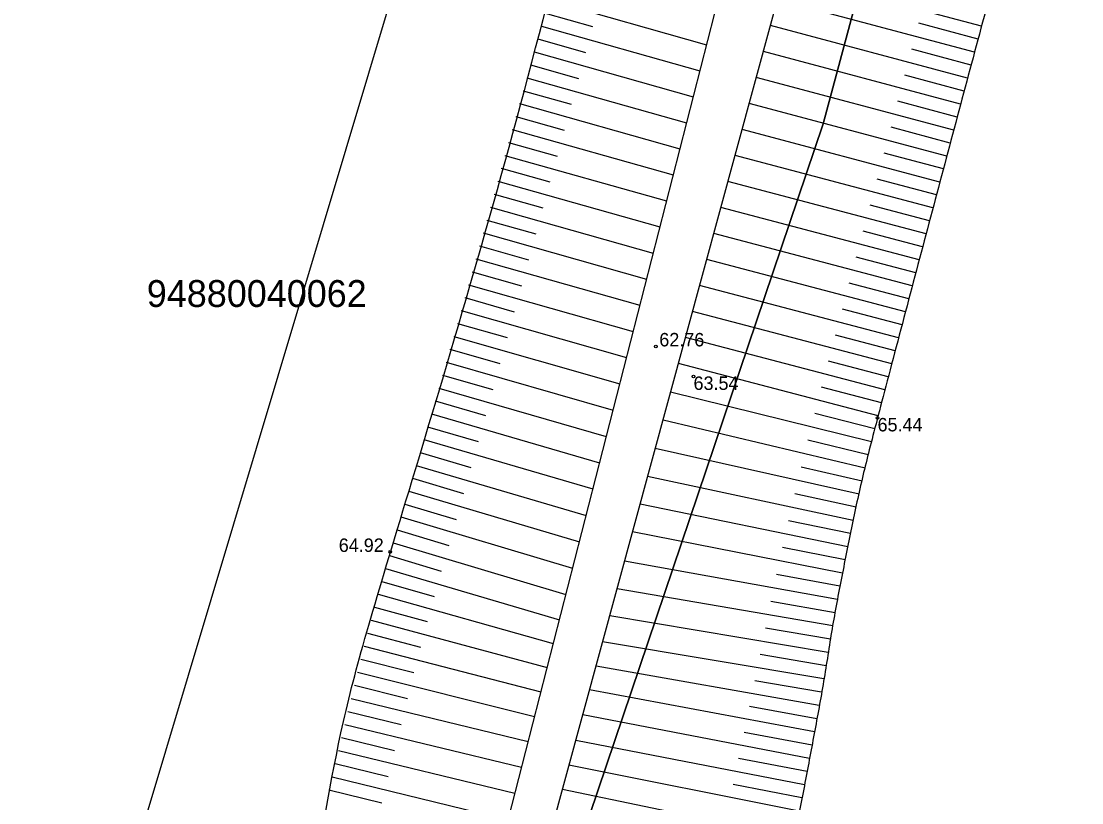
# Model space of a CAD drawing. Extents: x 616607 to 617499, y 408385 to 409695.
# Drawn here: x 617215.1 to 617254.55, y 409366.67 to 409395.75 of the extents above; entities that cross this region are included whole.
import ezdxf

# ---------------------------------------------------------------- set-up
doc = ezdxf.new("R2010")
doc.units = 0
for name, color, linetype in [('HIDG_GRAV_####_####_#', 7, 'Continuous'), ('RAMI_UZMR_####_####_#', 7, 'Continuous'), ('RELJ_AATZ_####_TKST_#', 7, 'Continuous'), ('RELJ_ELEM_####_####_#', 7, 'Continuous'), ('RELJ_NOGA_####_####_#', 7, 'Continuous'), ('ROBZ_PROJ_####_####_#', 7, 'Continuous'), ('ROBZ_PROJ_####_TKST_#', 7, 'Continuous'), ('ROBZ_UZMR_####_####_#', 7, 'Continuous')]:
    doc.layers.add(name, color=color, linetype=linetype)

# ---------------------------------------------------------------- blocks, each defined once
blk = doc.blocks.new('PKT')
at = {"layer": 'RELJ_ELEM_####_####_#'}
blk.add_circle((0, 0), 0.05, dxfattribs=at)

msp = doc.modelspace()

# ---------------------------------------------------------------- linework, layer by layer
at = {"layer": 'HIDG_GRAV_####_####_#'}
for points in [[(617196.049, 409072.553), (617193.886, 409072.979), (617195.921, 409087.874), (617195.921, 409087.874), (617199.518, 409112.516), (617194.569, 409134.842), (617162.019, 409207.474), (617151.93, 409229.107), (617149.428, 409241.28), (617152.359, 409253.938), (617188.564, 409303.055), (617197.968, 409312.659), (617223.456, 409346.169), (617232.567, 409363.51), (617247.671, 409422.509), (617276.576, 409461.456), (617285.007, 409472.526), (617327.765, 409527.3)], [(617198.671, 409072.074), (617200.929, 409072.435), (617202.532, 409075.622), (617201.237, 409087.874), (617202.422, 409112.516), (617197.415, 409136.544), (617162.613, 409207.758), (617153.021, 409229.447), (617150.525, 409241.262), (617153.298, 409253.658), (617189.431, 409302.264), (617198.754, 409312.12), (617224.478, 409345.652), (617234.105, 409363.027), (617250.009, 409421.44), (617285.914, 409471.848), (617328.6, 409526.531)]]:
    msp.add_lwpolyline(points, dxfattribs=at)
at = {"layer": 'RAMI_UZMR_####_####_#'}
msp.add_lwpolyline([(617101.571, 408748.246), (617213.472, 409074.039), (617215.883, 409140.56), (617165.121, 409241.478), (617252.137, 409353.424), (617269.572, 409425.099), (617332.631, 409510.312), (617439.945, 409622.037), (617425.373, 409635.959), (617242.079, 409440.82), (617216.614, 409355.716), (617136.613, 409246.751), (617191.828, 409115.62), (617145.545, 408952.8)], dxfattribs=at)
at = {"layer": 'RELJ_NOGA_####_####_#'}
for p, q in [((617250.823, 409395.565), (617243.5, 409397.533)), ((617234.728, 409396.533), (617240.594, 409394.866)), ((617250.564, 409394.599), (617243.236, 409396.564)), ((617234.592, 409396.052), (617236.355, 409395.551)), ((617234.455, 409395.571), (617234.454, 409395.572)), ((617234.455, 409395.571), (617240.347, 409393.901)), ((617250.306, 409393.633), (617242.973, 409395.595)), ((617250.694, 409395.082), (617248.496, 409395.672)), ((617250.823, 409395.565), (617250.824, 409395.565)), ((617234.319, 409395.09), (617234.319, 409395.09)), ((617234.319, 409395.09), (617236.09, 409394.588)), ((617250.694, 409395.082), (617250.694, 409395.082)), ((617250.435, 409394.116), (617248.236, 409394.705)), ((617234.183, 409394.609), (617234.182, 409394.61)), ((617234.183, 409394.609), (617240.1, 409392.936)), ((617250.048, 409392.667), (617242.709, 409394.625)), ((617250.564, 409394.599), (617250.565, 409394.599)), ((617234.046, 409394.128), (617234.046, 409394.128)), ((617234.046, 409394.128), (617235.825, 409393.625)), ((617250.435, 409394.116), (617250.435, 409394.116)), ((617233.91, 409393.647), (617233.909, 409393.647)), ((617233.91, 409393.647), (617239.853, 409391.971)), ((617249.79, 409391.701), (617242.446, 409393.66)), ((617250.177, 409393.15), (617247.976, 409393.739)), ((617250.306, 409393.633), (617250.307, 409393.633)), ((617233.775, 409393.166), (617233.774, 409393.166)), ((617233.775, 409393.166), (617235.561, 409392.662)), ((617250.177, 409393.15), (617250.177, 409393.15)), ((617233.639, 409392.685), (617233.638, 409392.685)), ((617233.639, 409392.685), (617239.605, 409391.002)), ((617249.533, 409390.735), (617242.182, 409392.691)), ((617249.919, 409392.184), (617247.716, 409392.772)), ((617250.048, 409392.667), (617250.049, 409392.667)), ((617233.503, 409392.203), (617233.503, 409392.203)), ((617233.503, 409392.203), (617235.297, 409391.697)), ((617249.919, 409392.184), (617249.919, 409392.184)), ((617233.367, 409391.722), (617233.366, 409391.722)), ((617233.367, 409391.722), (617239.357, 409390.032)), ((617249.275, 409389.768), (617241.919, 409391.726)), ((617249.661, 409391.218), (617247.457, 409391.805)), ((617249.79, 409391.701), (617249.791, 409391.701)), ((617233.232, 409391.241), (617233.231, 409391.241)), ((617233.232, 409391.241), (617235.032, 409390.733)), ((617249.661, 409391.218), (617249.662, 409391.218)), ((617233.096, 409390.76), (617233.095, 409390.76)), ((617233.096, 409390.76), (617239.109, 409389.065)), ((617249.018, 409388.802), (617241.655, 409390.757)), ((617249.404, 409390.252), (617247.198, 409390.839)), ((617249.533, 409390.735), (617249.534, 409390.734)), ((617232.96, 409390.278), (617232.96, 409390.278)), ((617232.96, 409390.278), (617234.768, 409389.769)), ((617249.404, 409390.252), (617249.404, 409390.251)), ((617232.825, 409389.797), (617232.824, 409389.797)), ((617232.825, 409389.797), (617238.861, 409388.096)), ((617248.762, 409387.835), (617241.392, 409389.792)), ((617249.147, 409389.285), (617246.939, 409389.873)), ((617249.275, 409389.768), (617249.276, 409389.768)), ((617232.689, 409389.316), (617232.689, 409389.316)), ((617232.689, 409389.316), (617234.504, 409388.804)), ((617249.147, 409389.285), (617249.147, 409389.285)), ((617232.553, 409388.835), (617232.552, 409388.835)), ((617232.553, 409388.835), (617238.612, 409387.124)), ((617248.505, 409386.869), (617241.128, 409388.822)), ((617248.89, 409388.319), (617246.68, 409388.905)), ((617249.018, 409388.802), (617249.019, 409388.802)), ((617232.417, 409388.353), (617232.417, 409388.354)), ((617232.417, 409388.353), (617234.239, 409387.839)), ((617248.633, 409387.352), (617246.422, 409387.939)), ((617248.89, 409388.319), (617248.89, 409388.319)), ((617232.282, 409387.872), (617232.281, 409387.873)), ((617232.282, 409387.872), (617238.363, 409386.151)), ((617248.249, 409385.902), (617240.866, 409387.857)), ((617248.762, 409387.835), (617248.763, 409387.835)), ((617232.145, 409387.391), (617232.145, 409387.391)), ((617232.145, 409387.391), (617233.974, 409386.874)), ((617248.633, 409387.352), (617248.634, 409387.352)), ((617232.009, 409386.91), (617232.008, 409386.91)), ((617232.009, 409386.91), (617238.115, 409385.182)), ((617247.994, 409384.935), (617240.602, 409386.888)), ((617248.377, 409386.386), (617246.163, 409386.972)), ((617248.505, 409386.869), (617248.506, 409386.869)), ((617231.873, 409386.429), (617231.873, 409386.429)), ((617231.873, 409386.429), (617233.708, 409385.908)), ((617248.377, 409386.386), (617248.377, 409386.386)), ((617248.121, 409385.419), (617245.905, 409386.004)), ((617231.736, 409385.948), (617231.735, 409385.948)), ((617231.736, 409385.948), (617237.866, 409384.208)), ((617247.738, 409383.969), (617240.338, 409385.919)), ((617248.249, 409385.902), (617248.25, 409385.902)), ((617231.6, 409385.467), (617231.599, 409385.467)), ((617231.6, 409385.467), (617233.442, 409384.942)), ((617248.121, 409385.419), (617248.122, 409385.419)), ((617231.463, 409384.986), (617231.462, 409384.986)), ((617231.463, 409384.986), (617237.616, 409383.233)), ((617247.484, 409383.002), (617240.074, 409384.949)), ((617247.866, 409384.452), (617245.647, 409385.038)), ((617247.994, 409384.935), (617247.995, 409384.935)), ((617231.325, 409384.505), (617231.325, 409384.505)), ((617231.325, 409384.505), (617233.175, 409383.977)), ((617247.866, 409384.452), (617247.866, 409384.452)), ((617231.188, 409384.025), (617231.187, 409384.025)), ((617231.188, 409384.025), (617237.366, 409382.255)), ((617247.611, 409383.485), (617245.389, 409384.069)), ((617247.23, 409382.034), (617239.81, 409383.978)), ((617247.738, 409383.969), (617247.739, 409383.968)), ((617231.05, 409383.544), (617231.05, 409383.544)), ((617231.05, 409383.544), (617232.908, 409383.012)), ((617247.611, 409383.485), (617247.611, 409383.485)), ((617230.912, 409383.063), (617230.911, 409383.064)), ((617230.912, 409383.063), (617237.117, 409381.281)), ((617246.976, 409381.067), (617239.547, 409383.014)), ((617247.357, 409382.518), (617245.133, 409383.103)), ((617247.484, 409383.002), (617247.485, 409383.001)), ((617230.774, 409382.583), (617230.774, 409382.583)), ((617230.774, 409382.583), (617232.639, 409382.045)), ((617247.357, 409382.518), (617247.357, 409382.518)), ((617230.636, 409382.103), (617230.635, 409382.103)), ((617230.636, 409382.103), (617236.865, 409380.299)), ((617247.103, 409381.551), (617244.876, 409382.134)), ((617247.23, 409382.034), (617247.231, 409382.034)), ((617230.497, 409381.622), (617230.496, 409381.622)), ((617230.497, 409381.622), (617232.37, 409381.08)), ((617246.728, 409380.098), (617239.258, 409381.951)), ((617247.103, 409381.551), (617247.103, 409381.551)), ((617230.357, 409381.142), (617230.356, 409381.142)), ((617230.357, 409381.142), (617236.615, 409379.323)), ((617246.492, 409379.127), (617238.975, 409380.911)), ((617246.851, 409380.583), (617244.617, 409381.156)), ((617246.976, 409381.067), (617246.977, 409381.067)), ((617230.218, 409380.662), (617230.217, 409380.662)), ((617230.218, 409380.662), (617232.099, 409380.113)), ((617246.851, 409380.583), (617246.851, 409380.583)), ((617230.077, 409380.182), (617230.076, 409380.182)), ((617230.077, 409380.182), (617236.365, 409378.346)), ((617246.609, 409379.613), (617244.362, 409380.161)), ((617246.728, 409380.098), (617246.729, 409380.098)), ((617229.937, 409379.702), (617229.937, 409379.702)), ((617229.937, 409379.702), (617231.827, 409379.147)), ((617246.267, 409378.152), (617238.685, 409379.848)), ((617246.609, 409379.613), (617246.609, 409379.613)), ((617229.796, 409379.222), (617229.795, 409379.223)), ((617229.796, 409379.222), (617236.112, 409377.359)), ((617246.378, 409378.64), (617244.114, 409379.164)), ((617246.492, 409379.127), (617246.493, 409379.126)), ((617229.655, 409378.743), (617229.654, 409378.743)), ((617229.655, 409378.743), (617231.555, 409378.182)), ((617246.052, 409377.176), (617238.402, 409378.81)), ((617246.378, 409378.64), (617246.378, 409378.64)), ((617229.513, 409378.263), (617229.512, 409378.264)), ((617229.513, 409378.263), (617235.862, 409376.38)), ((617246.158, 409377.664), (617243.874, 409378.166)), ((617246.267, 409378.152), (617246.268, 409378.152)), ((617229.37, 409377.784), (617229.37, 409377.784)), ((617229.37, 409377.784), (617231.281, 409377.217)), ((617245.846, 409376.197), (617238.122, 409377.78)), ((617229.227, 409377.305), (617229.227, 409377.305)), ((617229.227, 409377.305), (617235.611, 409375.399)), ((617246.158, 409377.664), (617246.158, 409377.664)), ((617245.948, 409376.687), (617243.642, 409377.167)), ((617246.052, 409377.176), (617246.053, 409377.175)), ((617229.084, 409376.826), (617229.084, 409376.826)), ((617229.084, 409376.826), (617231.004, 409376.249)), ((617245.65, 409375.216), (617237.843, 409376.755)), ((617245.948, 409376.687), (617245.948, 409376.687)), ((617228.94, 409376.347), (617228.939, 409376.347)), ((617228.94, 409376.347), (617235.36, 409374.418)), ((617245.747, 409375.707), (617243.417, 409376.173)), ((617245.846, 409376.197), (617245.847, 409376.197)), ((617228.796, 409375.868), (617228.796, 409375.868)), ((617228.796, 409375.868), (617230.727, 409375.285)), ((617245.747, 409375.707), (617245.747, 409375.707)), ((617228.653, 409375.389), (617228.652, 409375.39)), ((617228.653, 409375.389), (617235.119, 409373.477)), ((617245.465, 409374.234), (617237.546, 409375.665)), ((617245.556, 409374.725), (617243.197, 409375.17)), ((617245.65, 409375.216), (617245.651, 409375.216)), ((617228.513, 409374.909), (617228.513, 409374.909)), ((617228.513, 409374.909), (617230.461, 409374.346)), ((617245.292, 409373.249), (617237.266, 409374.635)), ((617245.556, 409374.725), (617245.556, 409374.725)), ((617228.376, 409374.428), (617228.375, 409374.428)), ((617228.376, 409374.428), (617234.893, 409372.596)), ((617245.377, 409373.741), (617242.985, 409374.16)), ((617245.465, 409374.234), (617245.466, 409374.233)), ((617228.243, 409373.946), (617228.243, 409373.946)), ((617228.243, 409373.946), (617230.205, 409373.412)), ((617245.377, 409373.741), (617245.378, 409373.741)), ((617228.113, 409373.464), (617228.112, 409373.464)), ((617228.113, 409373.464), (617234.664, 409371.701)), ((617245.124, 409372.263), (617236.993, 409373.633)), ((617227.985, 409372.98), (617227.984, 409372.98)), ((617227.985, 409372.98), (617229.955, 409372.465)), ((617245.208, 409372.756), (617242.784, 409373.169)), ((617245.292, 409373.249), (617245.293, 409373.249)), ((617244.958, 409371.277), (617236.729, 409372.664)), ((617245.208, 409372.756), (617245.208, 409372.756)), ((617227.859, 409372.496), (617227.858, 409372.497)), ((617227.859, 409372.496), (617234.433, 409370.797)), ((617245.041, 409371.77), (617242.587, 409372.184)), ((617245.124, 409372.263), (617245.125, 409372.263)), ((617227.735, 409372.012), (617227.735, 409372.012)), ((617227.735, 409372.012), (617229.71, 409371.513)), ((617244.789, 409370.291), (617236.482, 409371.758)), ((617245.041, 409371.77), (617245.042, 409371.77)), ((617227.613, 409371.527), (617227.612, 409371.527)), ((617227.613, 409371.527), (617234.197, 409369.876)), ((617227.492, 409371.042), (617227.492, 409371.042)), ((617227.492, 409371.042), (617229.468, 409370.553)), ((617244.874, 409370.784), (617242.393, 409371.209)), ((617244.958, 409371.277), (617244.959, 409371.277)), ((617244.611, 409369.307), (617236.241, 409370.873)), ((617244.874, 409370.784), (617244.875, 409370.784)), ((617227.373, 409370.556), (617227.372, 409370.557)), ((617227.373, 409370.556), (617233.959, 409368.947)), ((617244.701, 409369.799), (617242.198, 409370.249)), ((617244.789, 409370.291), (617244.79, 409370.291)), ((617227.254, 409370.071), (617227.254, 409370.071)), ((617227.254, 409370.071), (617229.229, 409369.59)), ((617244.426, 409368.325), (617235.988, 409369.941)), ((617244.701, 409369.799), (617244.702, 409369.799)), ((617227.136, 409369.585), (617227.135, 409369.585)), ((617227.136, 409369.585), (617233.715, 409367.992)), ((617227.019, 409369.099), (617227.019, 409369.099)), ((617227.019, 409369.099), (617228.99, 409368.621)), ((617244.237, 409367.343), (617235.73, 409368.994)), ((617244.519, 409368.816), (617241.997, 409369.291)), ((617244.611, 409369.307), (617244.612, 409369.307)), ((617226.901, 409368.613), (617226.9, 409368.613)), ((617226.901, 409368.613), (617233.466, 409367.024)), ((617244.519, 409368.816), (617244.519, 409368.816)), ((617244.332, 409367.834), (617241.789, 409368.321)), ((617244.426, 409368.325), (617244.427, 409368.324)), ((617226.784, 409368.127), (617226.783, 409368.127)), ((617226.784, 409368.127), (617228.751, 409367.65)), ((617244.043, 409366.362), (617235.477, 409368.065)), ((617244.332, 409367.834), (617244.332, 409367.833)), ((617226.666, 409367.641), (617226.665, 409367.641)), ((617226.666, 409367.641), (617233.215, 409366.043)), ((617226.547, 409367.155), (617226.546, 409367.155)), ((617226.547, 409367.155), (617228.509, 409366.672)), ((617243.845, 409365.381), (617235.231, 409367.161)), ((617244.14, 409366.852), (617241.579, 409367.355)), ((617244.237, 409367.343), (617244.238, 409367.342)), ((617244.14, 409366.852), (617244.141, 409366.852))]:
    msp.add_line(p, q, dxfattribs=at)
for points in [[(617148.095, 409250.281), (617149.367, 409254.282), (617150.639, 409258.284), (617151.912, 409262.285), (617156.597, 409277.022), (617171.021, 409286.603), (617180.379, 409298.915), (617194.802, 409317.89), (617212.921, 409334.355), (617223.034, 409356.295), (617225.913, 409362.541), (617226.817, 409369.327), (617228.782, 409375.821), (617233.86, 409392.605), (617237.843, 409409.628), (617244.376, 409426.063), (617252.258, 409445.895), (617268.673, 409460.708), (617281.86, 409477.296), (617294.583, 409493.301), (617307.725, 409508.821), (617320.496, 409524.825), (617320.543, 409524.885), (617320.584, 409524.948), (617320.623, 409525.013), (617320.843, 409525.374), (617320.906, 409525.909), (617320.728, 409526.275), (617320.636, 409526.463), (617320.388, 409526.567), (617320.294, 409526.764), (617319.61, 409528.184), (617318.926, 409529.604), (617318.242, 409531.024)], [(617336.806, 409523.735), (617334.087, 409521.174), (617331.368, 409518.613), (617328.65, 409516.053), (617321.193, 409509.03), (617314.57, 409501.094), (617308.568, 409492.793), (617305.546, 409488.614), (617302.537, 409484.426), (617299.516, 409480.247), (617296.49, 409476.063), (617293.469, 409471.875), (617290.436, 409467.695), (617287.772, 409464.025), (617284.965, 409460.461), (617282.252, 409456.826), (617279.55, 409453.205), (617276.887, 409449.558), (617274.256, 409445.882), (617271.624, 409442.206), (617269.17, 409438.414), (617266.782, 409434.573), (617265.581, 409432.642), (617264.455, 409430.674), (617263.346, 409428.69), (617262.228, 409426.69), (617261.169, 409424.668), (617260.166, 409422.606), (617258.56, 409419.302), (617257.132, 409415.931), (617255.903, 409412.47), (617254.682, 409409.035), (617253.531, 409405.585), (617252.579, 409402.073), (617251.627, 409398.563), (617250.683, 409395.052), (617249.746, 409391.538), (617248.81, 409388.023), (617247.876, 409384.508), (617246.956, 409380.989), (617246.456, 409379.078), (617246.028, 409377.149), (617245.649, 409375.21), (617245.269, 409373.268), (617244.984, 409371.31), (617244.622, 409369.366), (617244.259, 409367.42), (617243.878, 409365.48), (617243.456, 409363.545), (617243.245, 409362.576), (617242.967, 409361.625), (617242.691, 409360.672), (617242.413, 409359.713), (617242.093, 409358.772), (617241.734, 409357.838), (617241.092, 409356.173), (617240.315, 409354.578), (617239.389, 409353.048), (617238.465, 409351.519), (617237.498, 409350.034), (617236.402, 409348.636), (617235.3, 409347.23), (617234.195, 409345.828), (617233.083, 409344.431), (617231.973, 409343.038), (617230.863, 409341.647), (617229.743, 409340.262), (617227.764, 409337.815), (617225.693, 409335.438), (617223.461, 409333.217), (617221.215, 409330.983), (617218.873, 409328.856), (617216.607, 409326.646), (617214.346, 409324.442), (617212.093, 409322.231), (617209.875, 409319.98), (617208.771, 409318.86), (617207.791, 409317.635), (617206.772, 409316.432), (617205.753, 409315.229), (617204.825, 409314.017), (617203.96, 409312.646), (617203.768, 409312.342), (617203.633, 409312.004), (617203.62, 409311.655), (617203.607, 409311.284), (617203.603, 409310.913), (617203.599, 409310.542), (617203.595, 409310.167), (617203.603, 409309.793), (617203.596, 409309.419), (617203.588, 409309.066), (617203.48, 409308.714), (617203.309, 409308.4), (617202.615, 409307.13), (617201.9, 409305.914), (617201.16, 409304.689), (617200.419, 409303.462), (617199.689, 409302.232), (617198.921, 409301.021), (617197.385, 409298.6), (617195.744, 409296.251), (617194.012, 409293.966), (617188.331, 409286.47), (617182.548, 409279.072), (617176.617, 409271.78), (617175.091, 409269.904), (617173.565, 409268.03), (617172.006, 409266.181), (617170.46, 409264.348), (617168.875, 409262.548), (617167.326, 409260.717), (617165.749, 409258.854), (617164.19, 409256.978), (617162.652, 409255.082), (617161.86, 409254.106), (617161.109, 409253.1), (617160.341, 409252.105), (617159.552, 409251.081), (617158.796, 409250.055), (617158.061, 409248.97), (617157.091, 409247.54), (617156.549, 409245.874), (617156.301, 409244.175), (617156.178, 409243.327), (617156.153, 409242.478), (617156.175, 409241.631), (617156.198, 409240.798), (617156.24, 409239.966), (617156.347, 409239.134), (617156.709, 409236.311), (617157.141, 409233.481), (617158.294, 409230.866), (617161.329, 409223.986), (617164.552, 409217.339), (617167.894, 409210.677), (617170.758, 409204.966), (617173.578, 409199.236), (617176.506, 409193.56), (617179.423, 409187.907), (617182.384, 409182.277), (617185.301, 409176.624), (617188.243, 409170.922), (617191.171, 409165.213), (617194.071, 409159.489), (617195.541, 409156.585), (617196.952, 409153.652), (617198.382, 409150.727), (617199.832, 409147.761), (617201.227, 409144.774), (617202.61, 409141.772), (617203.681, 409139.449), (617204.533, 409137.047), (617205.282, 409134.589), (617206.022, 409132.164), (617206.554, 409129.71), (617206.943, 409127.212), (617207.329, 409124.726), (617207.611, 409122.242), (617207.809, 409119.738), (617208.005, 409117.248), (617208.126, 409114.753), (617208.097, 409112.263), (617208.074, 409110.266), (617207.983, 409108.256), (617207.635, 409106.282), (617207.283, 409104.281), (617206.913, 409102.294), (617206.558, 409100.3), (617206.203, 409098.306), (617205.85, 409096.331), (617205.506, 409094.315), (617205.165, 409092.324), (617205.06, 409090.322), (617205.116, 409088.325), (617205.171, 409086.355), (617205.316, 409084.384), (617205.484, 409082.414), (617205.653, 409080.435), (617205.914, 409078.469), (617206.09, 409076.495), (617206.126, 409076.085), (617206.005, 409075.66), (617206.103, 409075.26)]]:
    msp.add_open_spline(points, degree=3, dxfattribs=at)
at = {"layer": 'ROBZ_PROJ_####_####_#'}
msp.add_lwpolyline([(617225.329, 409427.473), (617250.98, 409414.497), (617244.928, 409391.934), (617233.453, 409357.938), (617201.229, 409318.934), (617196.893, 409321.733), (617174.104, 409336.449)], dxfattribs=at)
at = {"layer": 'ROBZ_UZMR_####_####_#'}
msp.add_lwpolyline([(617232.583, 409073.745), (617196.025, 409075.262), (617200.886, 409119.423), (617196.507, 409136.07), (617150.138, 409230.13), (617148.652, 409247.272), (617201.229, 409318.934), (617233.453, 409357.938), (617244.928, 409391.934), (617250.98, 409414.497), (617255.789, 409432.426), (617326.39, 409521.291), (617332.188, 409529.592), (617332.358, 409529.835), (617335.391, 409534.333), (617341.051, 409533.641), (617349.913, 409536.856), (617370.73, 409556.7), (617378.749, 409547.935), (617381.343, 409545.1)], dxfattribs=at)

# ---------------------------------------------------------------- block references
at = {"layer": 'RELJ_ELEM_####_####_#'}
for p in [(617238.704, 409383.649), (617240.11, 409382.533), (617246.956, 409380.989), (617228.83, 409376.009)]:
    msp.add_blockref('PKT', p, dxfattribs=at)

# ---------------------------------------------------------------- texts
at = {"layer": 'RELJ_AATZ_####_TKST_#'}
for s, p in [('62.76', (617238.837, 409383.652)), ('63.54', (617240.11, 409382.033)), ('65.44', (617246.956, 409380.489)), ('64.92', (617226.912, 409376.005))]:
    msp.add_text(s, height=0.5, dxfattribs=at).set_placement(p)
at = {"layer": 'ROBZ_PROJ_####_TKST_#'}
msp.add_text('94880040062', height=1, dxfattribs=at).set_placement((617219.771, 409385.119))

doc.saveas('drawing.dxf')
